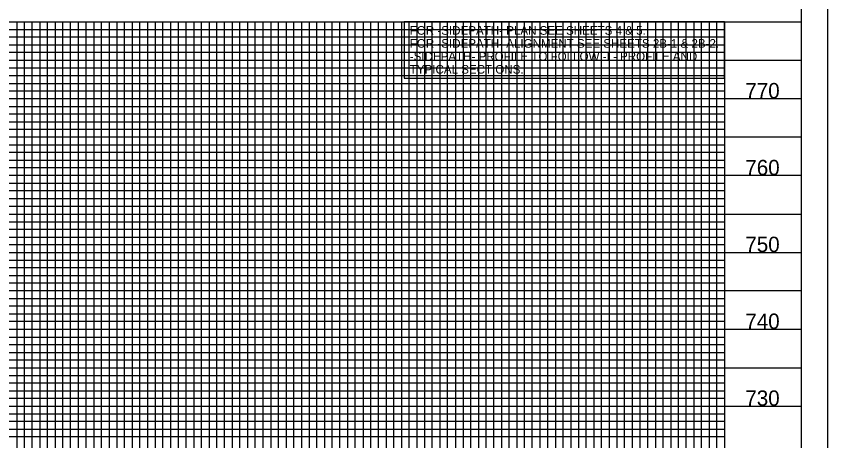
# Model space of a CAD drawing. Extents: x 1524869 to 1526553, y 501099 to 502199.
# Drawn here: x 1526026 to 1526553, y 501376 to 501652 of the extents above; entities that cross this region are included whole.
import ezdxf

# ---------------------------------------------------------------- set-up
doc = ezdxf.new("R2010")
doc.units = 0
for name, color, linetype in [('Exist Vertical Profile Vertical Axis Label', 7, 'Continuous'), ('Prop Grid Mask', 7, 'Continuous'), ('Prop Horizontal Alignment Curve and Spiral Data', 7, 'Continuous'), ('Sheet Layout Profile Border Port 2', 7, 'Continuous'), ('Sheet Plot Border Outside CELL', 7, 'Continuous'), ('Sheet Profile CELL', 7, 'Continuous'), ('Sheet Profile Grid Major CELL', 7, 'Continuous'), ('Sheet Profile Grid Middle CELL', 7, 'Continuous'), ('Sheet Profile Grid Minor CELL', 7, 'Continuous')]:
    doc.layers.add(name, color=color, linetype=linetype)

msp = doc.modelspace()

# ---------------------------------------------------------------- linework, layer by layer
at = {"layer": 'Prop Grid Mask'}
msp.add_lwpolyline([(1526277.89, 501612.02), (1526486.08, 501612.02), (1526486.08, 501648.56), (1526277.89, 501648.56)], close=True, dxfattribs=at)
at = {"layer": 'Sheet Layout Profile Border Port 2'}
msp.add_lwpolyline([(1525086.08, 501648.56), (1526486.08, 501648.56), (1526486.08, 501148.56), (1525086.08, 501148.56)], close=True, dxfattribs=at)
at = {"layer": 'Sheet Plot Border Outside CELL'}
msp.add_lwpolyline([(1524869.08, 501098.56), (1526553.08, 501098.56), (1526553.08, 502198.56), (1524869.08, 502198.56)], close=True, dxfattribs=at)
at = {"layer": 'Sheet Profile CELL'}
msp.add_line((1525036.08, 501648.56), (1526536.08, 501648.56), dxfattribs=at)
msp.add_lwpolyline([(1526536.08, 502173.56), (1525036.08, 502173.56), (1525036.08, 501123.56), (1526536.08, 501123.56)], close=True, dxfattribs=at)
at = {"layer": 'Sheet Profile Grid Major CELL'}
for p, q in [((1526036.08, 501648.56), (1526086.08, 501648.56)), ((1526136.08, 501648.56), (1526186.08, 501648.56)), ((1526236.08, 501648.56), (1526286.08, 501648.56)), ((1526336.08, 501648.56), (1526386.08, 501648.56)), ((1526377.02, 501648.56), (1526427.02, 501648.56))]:
    msp.add_line(p, q, dxfattribs=at)
for points in [[(1525986.08, 501148.56), (1526036.08, 501148.56), (1526036.08, 501648.56), (1526086.08, 501648.56), (1526086.08, 501148.56), (1526136.08, 501148.56), (1526136.08, 501648.56), (1526186.08, 501648.56), (1526186.08, 501148.56), (1526236.08, 501148.56), (1526236.08, 501648.56), (1526286.08, 501648.56), (1526286.08, 501148.56), (1526336.08, 501148.56), (1526336.08, 501648.56), (1526386.08, 501648.56), (1526386.08, 501148.56), (1526436.08, 501148.56), (1526436.08, 501148.56), (1526436.08, 501648.56), (1526486.08, 501648.56), (1526486.08, 501148.56)], [(1526536.08, 501598.56), (1525036.08, 501598.56)], [(1526536.08, 501548.56), (1525036.08, 501548.56), (1525036.08, 501498.56), (1526536.08, 501498.56)], [(1526536.08, 501448.56), (1525036.08, 501448.56), (1525036.08, 501398.56), (1526536.08, 501398.56)]]:
    msp.add_lwpolyline(points, dxfattribs=at)
at = {"layer": 'Sheet Profile Grid Middle CELL'}
for points in [[(1526011.08, 501148.56), (1526061.08, 501148.56), (1526061.08, 501648.56), (1526111.08, 501648.56), (1526111.08, 501148.56), (1526161.08, 501148.56), (1526161.08, 501648.56), (1526211.08, 501648.56), (1526211.08, 501148.56), (1526261.08, 501148.56), (1526261.08, 501648.56), (1526311.08, 501648.56), (1526311.08, 501148.56), (1526361.08, 501148.56), (1526361.08, 501648.56), (1526411.08, 501648.56), (1526411.08, 501148.56), (1526461.08, 501148.56), (1526461.08, 501648.56)], [(1525036.08, 501623.56), (1526536.08, 501623.56)], [(1526536.08, 501573.56), (1525036.08, 501573.56), (1525036.08, 501523.56), (1526536.08, 501523.56)], [(1526536.08, 501473.56), (1525036.08, 501473.56), (1525036.08, 501423.56), (1526536.08, 501423.56)]]:
    msp.add_lwpolyline(points, dxfattribs=at)
at = {"layer": 'Sheet Profile Grid Minor CELL'}
for p, q in [((1525086.08, 501643.56), (1526486.08, 501643.56)), ((1526486.08, 501638.56), (1525086.08, 501638.56)), ((1525086.08, 501633.56), (1526486.08, 501633.56)), ((1526486.08, 501628.56), (1525086.08, 501628.56)), ((1525086.08, 501618.56), (1526486.08, 501618.56)), ((1526486.08, 501613.56), (1525086.08, 501613.56)), ((1525086.08, 501608.56), (1526486.08, 501608.56)), ((1526486.08, 501603.56), (1525086.08, 501603.56)), ((1525086.08, 501593.56), (1526486.08, 501593.56)), ((1526486.08, 501588.56), (1525086.08, 501588.56)), ((1525086.08, 501583.56), (1526486.08, 501583.56)), ((1526486.08, 501578.56), (1525086.08, 501578.56)), ((1525086.08, 501568.56), (1526486.08, 501568.56)), ((1526486.08, 501563.56), (1525086.08, 501563.56)), ((1525086.08, 501558.56), (1526486.08, 501558.56)), ((1526486.08, 501553.56), (1525086.08, 501553.56)), ((1525086.08, 501543.56), (1526486.08, 501543.56)), ((1526486.08, 501538.56), (1525086.08, 501538.56)), ((1525086.08, 501533.56), (1526486.08, 501533.56)), ((1526486.08, 501528.56), (1525086.08, 501528.56)), ((1525086.08, 501518.56), (1526486.08, 501518.56)), ((1526486.08, 501513.56), (1525086.08, 501513.56)), ((1525086.08, 501508.56), (1526486.08, 501508.56)), ((1526486.08, 501503.56), (1525086.08, 501503.56)), ((1525086.08, 501493.56), (1526486.08, 501493.56)), ((1526486.08, 501488.56), (1525086.08, 501488.56)), ((1525086.08, 501483.56), (1526486.08, 501483.56)), ((1526486.08, 501478.56), (1525086.08, 501478.56)), ((1525086.08, 501468.56), (1526486.08, 501468.56)), ((1526486.08, 501463.56), (1525086.08, 501463.56)), ((1525086.08, 501458.56), (1526486.08, 501458.56)), ((1526486.08, 501453.56), (1525086.08, 501453.71)), ((1525086.08, 501443.56), (1526486.08, 501443.56)), ((1526486.08, 501438.56), (1525086.08, 501438.56)), ((1525086.08, 501433.56), (1526486.08, 501433.56)), ((1526486.08, 501428.56), (1525086.08, 501428.56)), ((1525086.08, 501418.56), (1526486.08, 501418.56)), ((1526486.08, 501413.56), (1525086.08, 501413.56)), ((1525086.08, 501408.56), (1526486.08, 501408.56)), ((1526486.08, 501403.56), (1525086.08, 501403.56)), ((1525086.08, 501393.56), (1526486.08, 501393.56)), ((1526486.08, 501388.56), (1525086.08, 501388.56)), ((1525086.08, 501383.56), (1526486.08, 501383.56)), ((1526486.08, 501378.56), (1525086.08, 501378.56))]:
    msp.add_line(p, q, dxfattribs=at)
for points in [[(1526021.08, 501648.56), (1526026.08, 501648.56), (1526026.08, 501148.56)], [(1526031.08, 501148.56), (1526031.08, 501648.56), (1526041.08, 501648.56), (1526041.08, 501148.56)], [(1526046.08, 501148.56), (1526046.08, 501648.56), (1526051.08, 501648.56), (1526051.08, 501148.56)], [(1526056.08, 501148.56), (1526056.08, 501648.56), (1526066.08, 501648.56), (1526066.08, 501148.56)], [(1526071.08, 501148.56), (1526071.08, 501648.56), (1526076.08, 501648.56), (1526076.08, 501148.56)], [(1526081.08, 501148.56), (1526081.08, 501648.56), (1526091.08, 501648.56), (1526091.08, 501148.56)], [(1526096.08, 501148.56), (1526096.08, 501648.56), (1526101.08, 501648.56), (1526101.08, 501148.56)], [(1526106.08, 501148.56), (1526106.08, 501648.56), (1526116.08, 501648.56), (1526116.08, 501148.56)], [(1526121.08, 501148.56), (1526121.08, 501648.56), (1526126.08, 501648.56), (1526126.08, 501148.56)], [(1526131.08, 501148.56), (1526131.08, 501648.56), (1526141.08, 501648.56), (1526141.08, 501148.56)], [(1526146.08, 501148.56), (1526146.08, 501648.56), (1526151.08, 501648.56), (1526151.08, 501148.56)], [(1526156.08, 501148.56), (1526156.08, 501648.56), (1526166.08, 501648.56), (1526166.08, 501148.56)], [(1526171.08, 501148.56), (1526171.08, 501648.56), (1526176.08, 501648.56), (1526176.08, 501148.56)], [(1526181.08, 501148.56), (1526181.08, 501648.56), (1526191.08, 501648.56), (1526191.08, 501148.56)], [(1526196.08, 501148.56), (1526196.08, 501648.56), (1526201.08, 501648.56), (1526201.08, 501148.56)], [(1526206.08, 501148.56), (1526206.08, 501648.56), (1526216.08, 501648.56), (1526216.08, 501148.56)], [(1526221.08, 501148.56), (1526221.08, 501648.56), (1526226.08, 501648.56), (1526226.08, 501148.56)], [(1526231.08, 501148.56), (1526231.08, 501648.56), (1526241.08, 501648.56), (1526241.08, 501148.56)], [(1526246.08, 501148.56), (1526246.08, 501648.56), (1526251.08, 501648.56), (1526251.08, 501148.56)], [(1526256.08, 501148.56), (1526256.08, 501648.56), (1526266.08, 501648.56), (1526266.08, 501148.56)], [(1526271.08, 501148.56), (1526271.08, 501648.56), (1526276.08, 501648.56), (1526276.08, 501148.56)], [(1526281.08, 501148.56), (1526281.08, 501648.56), (1526291.08, 501648.56), (1526291.08, 501148.56)], [(1526296.08, 501148.56), (1526296.08, 501648.56), (1526301.08, 501648.56), (1526301.08, 501148.56)], [(1526306.08, 501148.56), (1526306.08, 501648.56), (1526316.08, 501648.56), (1526316.08, 501148.56)], [(1526321.08, 501148.56), (1526321.08, 501648.56), (1526326.08, 501648.56), (1526326.08, 501148.56)], [(1526331.08, 501148.56), (1526331.08, 501648.56), (1526341.08, 501648.56), (1526341.08, 501148.56)], [(1526346.08, 501148.56), (1526346.08, 501648.56), (1526351.08, 501648.56), (1526351.08, 501148.56)], [(1526356.08, 501148.56), (1526356.08, 501648.56), (1526366.08, 501648.56), (1526366.08, 501148.56)], [(1526371.08, 501148.56), (1526371.08, 501648.56), (1526376.08, 501648.56), (1526376.08, 501148.56)], [(1526381.08, 501148.56), (1526381.08, 501648.56), (1526391.08, 501648.56), (1526391.08, 501148.56)], [(1526396.08, 501148.56), (1526396.08, 501648.56), (1526401.08, 501648.56), (1526401.08, 501148.56)], [(1526406.08, 501148.56), (1526406.08, 501648.56), (1526416.08, 501648.56), (1526416.08, 501148.56)], [(1526421.08, 501148.56), (1526421.08, 501648.56), (1526426.08, 501648.56), (1526426.08, 501148.56)], [(1526431.08, 501148.56), (1526431.08, 501648.56), (1526441.08, 501648.56), (1526441.08, 501148.56)], [(1526446.08, 501148.56), (1526446.08, 501648.56), (1526451.08, 501648.56), (1526451.08, 501148.56)], [(1526456.08, 501148.56), (1526456.08, 501648.56), (1526466.08, 501648.56), (1526466.08, 501148.56)], [(1526471.08, 501148.56), (1526471.08, 501648.56), (1526476.08, 501648.56), (1526476.08, 501148.56)], [(1526481.08, 501148.56), (1526481.08, 501648.56), (1526486.08, 501648.56)]]:
    msp.add_lwpolyline(points, dxfattribs=at)

# ---------------------------------------------------------------- texts
at = {"layer": 'Exist Vertical Profile Vertical Axis Label'}
for s, p in [('770', (1526499.51, 501598.81)), ('760', (1526499.51, 501548.81)), ('750', (1526499.51, 501498.81)), ('740', (1526499.51, 501448.81)), ('730', (1526499.51, 501398.81))]:
    msp.add_text(s, height=10, dxfattribs=at).set_placement(p)
at = {"layer": 'Prop Horizontal Alignment Curve and Spiral Data'}
for s, p in [('FOR -SIDEPATH- PLAN SEE SHEETS 4 & 5.', (1526281.45, 501640.18)), ('FOR -SIDEPATH- ALIGNMENT SEE SHEETS 2B-1 & 2B-2.', (1526281.45, 501631.74)), ('-SIDEPATH- PROFILE TO FOLLOW -L- PROFILE AND', (1526281.45, 501623.3)), ('TYPICAL SECTIONS.', (1526281.45, 501614.87))]:
    msp.add_text(s, height=5.625, rotation=360, dxfattribs=at).set_placement(p)

doc.saveas('drawing.dxf')
